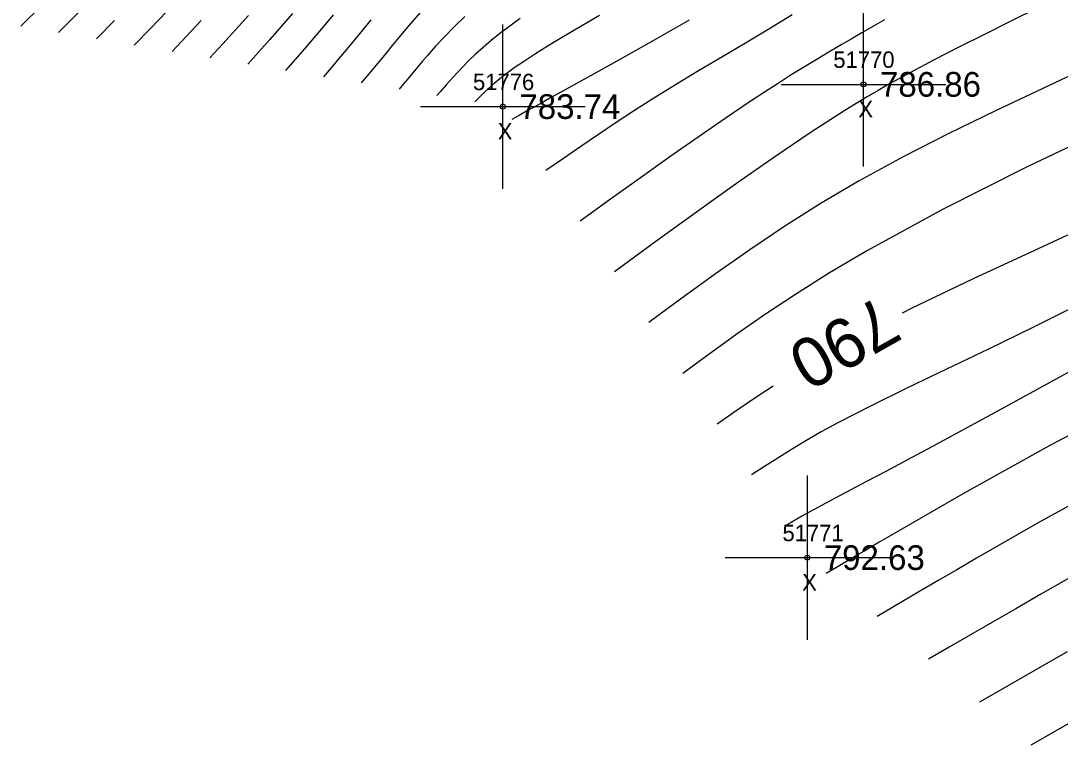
# Model space of a CAD drawing. Extents: x 1378535 to 1380697, y 997729 to 1000024.
# Drawn here: x 1379668.5 to 1379731.7, y 998768.3 to 998812.4 of the extents above; entities that cross this region are included whole.
import ezdxf

# ---------------------------------------------------------------- set-up
doc = ezdxf.new("R2010")
doc.units = 0
for name, color, linetype in [('RD_DTM_Major1', 7, 'Continuous'), ('RD_DTM_Major1_Lbl', 7, 'Continuous'), ('RD_DTM_Minor1', 7, 'Continuous'), ('RD_EX_Misc', 7, 'Continuous'), ('RD_EX_Misc_txCode', 7, 'Continuous'), ('RD_EX_TX_Misc_ELEV', 7, 'Continuous'), ('RD_SMD_Locator', 7, 'Continuous')]:
    doc.layers.add(name, color=color, linetype=linetype)

msp = doc.modelspace()

# ---------------------------------------------------------------- linework, layer by layer
at = {"layer": 'RD_DTM_Major1'}
for points in [[(1379679.5, 998812.397), (1379678.616, 998811.453), (1379677.735, 998810.524)], [(1379692.807, 998812.896), (1379692.135, 998812.113), (1379691.51, 998811.365), (1379691.103, 998810.875), (1379690.71, 998810.401), (1379690.33, 998809.94), (1379689.592, 998809.045), (1379689.229, 998808.605)], [(1379715.398, 998812.738), (1379713.989, 998811.877), (1379712.566, 998811.025), (1379711.141, 998810.179), (1379709.723, 998809.336), (1379708.322, 998808.491), (1379706.95, 998807.643), (1379705.825, 998806.925), (1379704.722, 998806.203), (1379703.638, 998805.478), (1379702.567, 998804.75), (1379701.506, 998804.021), (1379700.448, 998803.29)], [(1379734.37, 998800.389), (1379730.382, 998798.55), (1379726.408, 998796.702), (1379722.633, 998794.887), (1379722.081, 998794.603)], [(1379714.254, 998790.171), (1379713.325, 998789.56), (1379712.073, 998788.71), (1379710.852, 998787.865)], [(1379763.221, 998789.817), (1379762.848, 998789.837), (1379760.383, 998789.767), (1379757.751, 998789.471), (1379754.973, 998788.916), (1379751.047, 998787.733), (1379747.012, 998786.148), (1379742.987, 998784.295), (1379739.09, 998782.307), (1379735.44, 998780.317), (1379732.157, 998778.457), (1379730.511, 998777.514), (1379728.993, 998776.64), (1379727.577, 998775.822), (1379724.949, 998774.296), (1379723.686, 998773.561)]]:
    msp.add_lwpolyline(points, dxfattribs=at)
at = {"layer": 'RD_DTM_Minor1'}
for points in [[(1379669.835, 998813.328), (1379668.54, 998812.059)], [(1379677.411, 998812.96), (1379676.421, 998811.925), (1379675.436, 998810.908)], [(1379730.374, 998813.201), (1379728.699, 998812.364), (1379727.087, 998811.558), (1379725.534, 998810.775), (1379724.036, 998810.006), (1379722.59, 998809.241), (1379721.932, 998808.884), (1379721.279, 998808.522), (1379720.625, 998808.151), (1379719.966, 998807.766), (1379719.294, 998807.364), (1379718.604, 998806.94), (1379716.551, 998805.617), (1379714.345, 998804.123), (1379712.018, 998802.492), (1379709.599, 998800.758), (1379707.12, 998798.956), (1379704.61, 998797.12)], [(1379741.008, 998813.313), (1379738.722, 998812.176), (1379736.348, 998810.997), (1379733.51, 998809.629), (1379730.636, 998808.271), (1379727.759, 998806.908), (1379724.916, 998805.528), (1379722.141, 998804.116), (1379719.468, 998802.658), (1379717.168, 998801.295), (1379714.961, 998799.892), (1379712.828, 998798.456), (1379710.751, 998796.996), (1379708.711, 998795.519), (1379706.69, 998794.035)], [(1379672.031, 998812.862), (1379670.838, 998811.675)], [(1379674.227, 998812.394), (1379673.137, 998811.291)], [(1379682.374, 998812.703), (1379681.588, 998811.829), (1379680.809, 998810.979), (1379680.034, 998810.14)], [(1379685.046, 998812.829), (1379684.357, 998812.029), (1379683.677, 998811.256), (1379683.003, 998810.501), (1379682.332, 998809.756)], [(1379687.524, 998812.752), (1379686.927, 998812.034), (1379686.342, 998811.345), (1379685.767, 998810.676), (1379685.197, 998810.021), (1379684.631, 998809.372)], [(1379689.814, 998812.443), (1379689.306, 998811.822), (1379688.813, 998811.226), (1379688.331, 998810.649), (1379687.859, 998810.087), (1379687.393, 998809.535), (1379686.93, 998808.988)], [(1379695.512, 998812.644), (1379694.865, 998812.021), (1379694.278, 998811.418), (1379693.744, 998810.839), (1379693.254, 998810.285), (1379692.94, 998809.921), (1379692.64, 998809.568), (1379692.352, 998809.223), (1379692.072, 998808.886), (1379691.798, 998808.552), (1379691.527, 998808.221)], [(1379698.882, 998812.532), (1379697.65, 998811.616), (1379697.112, 998811.181), (1379696.622, 998810.76), (1379696.175, 998810.354), (1379695.767, 998809.961), (1379695.393, 998809.583), (1379695.048, 998809.22), (1379694.826, 998808.979), (1379694.615, 998808.744), (1379694.411, 998808.513), (1379694.018, 998808.061), (1379693.826, 998807.837)], [(1379703.706, 998812.705), (1379702.284, 998811.88), (1379701.396, 998811.355), (1379700.573, 998810.856), (1379699.818, 998810.383), (1379699.133, 998809.937), (1379698.519, 998809.517), (1379697.98, 998809.123), (1379697.739, 998808.936), (1379697.516, 998808.756), (1379697.309, 998808.581), (1379697.115, 998808.411), (1379696.933, 998808.246), (1379696.761, 998808.085), (1379696.649, 998807.977), (1379696.54, 998807.87), (1379696.434, 998807.765), (1379696.227, 998807.557), (1379696.125, 998807.453)], [(1379709.154, 998812.43), (1379707.013, 998811.201), (1379704.928, 998810.032), (1379702.962, 998808.943), (1379701.176, 998807.954), (1379700.673, 998807.674), (1379700.19, 998807.403), (1379699.721, 998807.139), (1379699.264, 998806.882), (1379698.814, 998806.627), (1379698.368, 998806.375)], [(1379721.021, 998812.437), (1379720.304, 998812.034), (1379719.629, 998811.649), (1379718.989, 998811.278), (1379718.377, 998810.919), (1379717.787, 998810.57), (1379716.962, 998810.075), (1379716.155, 998809.585), (1379715.354, 998809.09), (1379714.545, 998808.58), (1379713.716, 998808.046), (1379712.853, 998807.478), (1379711.328, 998806.447), (1379709.696, 998805.318), (1379707.979, 998804.109), (1379706.198, 998802.841), (1379704.374, 998801.533), (1379702.529, 998800.205)], [(1379734.969, 998806.018), (1379729.677, 998803.507), (1379724.572, 998800.923), (1379719.99, 998798.42), (1379717.674, 998797.053), (1379715.601, 998795.752), (1379713.723, 998794.505), (1379711.992, 998793.298), (1379710.357, 998792.117), (1379708.771, 998790.95)], [(1379732.822, 998795.145), (1379730.037, 998793.738), (1379727.343, 998792.424), (1379724.776, 998791.195), (1379722.369, 998790.043), (1379720.159, 998788.96), (1379718.18, 998787.938), (1379717.176, 998787.386), (1379716.243, 998786.848), (1379715.366, 998786.321), (1379714.531, 998785.802), (1379713.725, 998785.29), (1379712.932, 998784.78)], [(1379732.57, 998791.216), (1379727.911, 998788.68), (1379723.893, 998786.479), (1379722.414, 998785.682), (1379721.097, 998784.98), (1379719.929, 998784.364), (1379717.987, 998783.343), (1379717.186, 998782.915), (1379716.778, 998782.692), (1379716.394, 998782.48), (1379716.031, 998782.276), (1379715.346, 998781.886), (1379715.013, 998781.695)], [(1379736.688, 998789.522), (1379731.063, 998786.562), (1379725.863, 998783.669), (1379721.404, 998781.099), (1379720.695, 998780.684), (1379720.015, 998780.285), (1379719.359, 998779.898), (1379718.093, 998779.151), (1379717.471, 998778.784)], [(1379734.667, 998784.233), (1379730.308, 998781.833), (1379726.606, 998779.712), (1379725.402, 998779.012), (1379724.307, 998778.372), (1379723.299, 998777.78), (1379721.456, 998776.692), (1379720.579, 998776.173)], [(1379732.111, 998774.009), (1379730.309, 998772.975), (1379726.793, 998770.95)], [(1379732.22, 998769.668), (1379729.9, 998768.338)]]:
    msp.add_lwpolyline(points, dxfattribs=at)
at = {"layer": 'RD_EX_Misc'}
for p, q in [((1379719.741, 998803.521), (1379719.741, 998813.521)), ((1379697.833, 998802.168), (1379697.833, 998812.168)), ((1379714.741, 998808.521), (1379724.741, 998808.521)), ((1379692.833, 998807.168), (1379702.833, 998807.168)), ((1379716.328, 998774.745), (1379716.328, 998784.745)), ((1379711.328, 998779.745), (1379721.328, 998779.745))]:
    msp.add_line(p, q, dxfattribs=at)
at = {"layer": 'RD_SMD_Locator'}
for centre in [(1379719.741, 998808.521), (1379697.833, 998807.168), (1379716.328, 998779.745)]:
    msp.add_circle(centre, 0.15, dxfattribs=at)

# ---------------------------------------------------------------- texts
at = {"layer": 'RD_DTM_Major1_Lbl'}
msp.add_text('790', height=3, rotation=209.52114, dxfattribs=at).set_placement((1379720.752, 998795.732))
at = {"layer": 'RD_EX_Misc_txCode'}
for s, p in [('51770', (1379717.906, 998809.521)), ('51776', (1379696.014, 998808.168)), ('X', (1379719.426, 998806.521)), ('X', (1379697.518, 998805.168)), ('51771', (1379714.816, 998780.745)), ('X', (1379716.013, 998777.745))]:
    msp.add_text(s, height=1, dxfattribs=at).set_placement(p)
at = {"layer": 'RD_EX_TX_Misc_ELEV'}
for s, p in [('786.86', (1379720.741, 998807.771)), ('783.74', (1379698.833, 998806.418)), ('792.63', (1379717.328, 998778.995))]:
    msp.add_text(s, height=1.5, dxfattribs=at).set_placement(p)

doc.saveas('drawing.dxf')
